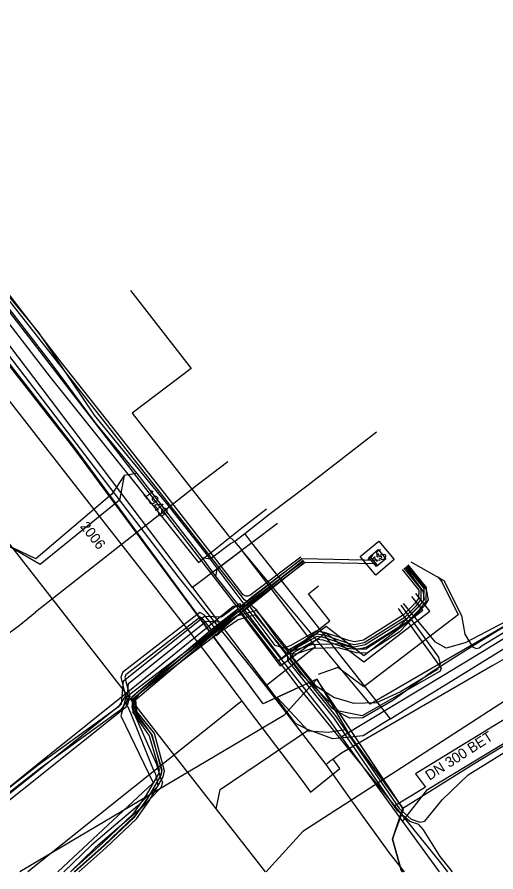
# Model space of a CAD drawing. Extents: x -600391 to -599491, y -1160176 to -1159402.
# Drawn here: x -600182.8 to -600145.4, y -1160176.1 to -1160109.3 of the extents above; entities that cross this region are included whole.
import ezdxf

# ---------------------------------------------------------------- set-up
doc = ezdxf.new("R2010")
doc.units = 0
for name, color, linetype in [('25', 7, 'Continuous'), ('CETIN_linie', 7, 'Continuous'), ('Vrstva 12', 7, 'Continuous'), ('Vrstva 13', 7, 'Continuous'), ('Vrstva 15', 7, 'Continuous'), ('Vrstva 16', 7, 'Continuous'), ('Vrstva 19', 7, 'Continuous'), ('Vrstva 42', 7, 'Continuous'), ('Vrstva 43', 7, 'Continuous'), ('Vrstva 44', 7, 'Continuous'), ('Vrstva 45', 7, 'Continuous'), ('Vrstva 55', 7, 'Continuous'), ('Vrstva 58', 7, 'Continuous'), ('Vrstva 9', 7, 'Continuous')]:
    doc.layers.add(name, color=color, linetype=linetype)

# ---------------------------------------------------------------- blocks, each defined once
blk = doc.blocks.new('NN640')
at = {"layer": '25'}
for points in [[(-1.89, 1.89), (1.89, 1.89)], [(-1.89, -1.89), (-1.89, 1.89)], [(1.89, 1.89), (1.89, -1.89)], [(-1.26, 0.79), (-0.22, 0.79)], [(-0.73, 0.79), (-0.73, -0.79)], [(1.2, 0.66), (0.94, 0.79), (0.66, 0.79), (0.41, 0.66), (0.28, 0.47), (0.28, 0.41), (0.41, 0.22), (1.13, -0.16), (1.26, -0.32), (1.26, -0.47), (1.13, -0.66), (0.91, -0.79), (0.63, -0.79), (0.5, -0.73), (0.28, -0.6)], [(1.89, -1.89), (-1.89, -1.89)]]:
    blk.add_lwpolyline(points, dxfattribs=at)
blk = doc.blocks.new('VN640')
at = {"layer": '25'}
for points in [[(-1.89, 1.89), (1.89, 1.89)], [(-1.89, -1.89), (-1.89, 1.89)], [(-1.26, 0.79), (-0.22, 0.79)], [(-0.73, 0.79), (-0.73, -0.79)], [(1.2, 0.66), (0.94, 0.79), (0.66, 0.79), (0.41, 0.66), (0.28, 0.47), (0.28, 0.41), (0.41, 0.22), (1.13, -0.16), (1.26, -0.32), (1.26, -0.47), (1.13, -0.66), (0.91, -0.79), (0.63, -0.79), (0.5, -0.73), (0.28, -0.6)], [(1.89, 1.89), (1.89, -1.89)], [(1.89, -1.89), (-1.89, -1.89)]]:
    blk.add_lwpolyline(points, dxfattribs=at)

msp = doc.modelspace()

# ---------------------------------------------------------------- linework, layer by layer
at = {"layer": 'CETIN_linie'}
for p, q in [((-600160.041, -1160145.829), (-600154.702, -1160141.703)), ((-600173.44, -1160144.95), (-600174.41, -1160145.12)), ((-600173.44, -1160144.95), (-600168.34, -1160151.51)), ((-600163.02, -1160148.09), (-600160.041, -1160145.829)), ((-600165, -1160149.65), (-600163.02, -1160148.09)), ((-600162.44, -1160148.85), (-600164.44, -1160150.36)), ((-600165.79, -1160150.27), (-600165, -1160149.65)), ((-600165.79, -1160150.27), (-600165.23, -1160150.94)), ((-600164.44, -1160150.36), (-600165, -1160149.65)), ((-600164.44, -1160150.36), (-600169.07, -1160153.86)), ((-600153.62, -1160164.12), (-600164.44, -1160150.36)), ((-600168.34, -1160151.51), (-600167.26, -1160153.04)), ((-600169.07, -1160153.86), (-600163.31, -1160161.48)), ((-600146.43, -1160159.67), (-600143.85, -1160158.08)), ((-600148.06, -1160160.68), (-600146.43, -1160159.67)), ((-600152.25, -1160163.27), (-600148.06, -1160160.68)), ((-600153.62, -1160164.12), (-600152.25, -1160163.27)), ((-600153.62, -1160164.12), (-600154.13, -1160164.44)), ((-600158.11, -1160165.69), (-600160.03, -1160164.97)), ((-600154.13, -1160164.44), (-600155.76, -1160165.44)), ((-600155.76, -1160165.44), (-600158.11, -1160165.69)), ((-600157.46, -1160165.52), (-600152.67, -1160172.13)), ((-600167.22, -1160171.18), (-600163.391, -1160176.079)), ((-600152.67, -1160172.13), (-600149.807, -1160176.079))]:
    msp.add_line(p, q, dxfattribs=at)
for points in [[(-600155.82, -1159824.25), (-600131.59, -1159876.14), (-600105.43, -1159931.66), (-600079.78, -1159985.02), (-600054.68, -1160038.07), (-600031.21, -1160088.32), (-600065.96, -1160109.81), (-600092.69, -1160126.24), (-600115.43, -1160139.89), (-600155.2, -1160162.97), (-600165.23, -1160150.94)], [(-600267.76, -1160025.17), (-600244.25, -1160055.86), (-600225.67, -1160079.89), (-600215.81, -1160092.29), (-600192.29, -1160121.78), (-600180.19, -1160137.43), (-600168.62, -1160151.9), (-600165.36, -1160149.31), (-600163.31, -1160147.71)], [(-600225.43, -1160097.28), (-600224.31, -1160097.79), (-600223.76, -1160098.18), (-600216.62, -1160107.61), (-600209.03, -1160117.53), (-600185.54, -1160147.75), (-600167.22, -1160171.18)], [(-600180.83, -1160138.31), (-600184.6, -1160133.37), (-600195.65, -1160118.9), (-600200.37, -1160112.86)], [(-600194.75, -1160117.41), (-600192.3, -1160120.58), (-600180.04, -1160136.48), (-600176.68, -1160141), (-600173.44, -1160144.95)], [(-600173.91, -1160130.65), (-600169.19, -1160136.75), (-600173.79, -1160140.24), (-600166.26, -1160149.83), (-600165.79, -1160150.27)], [(-600169.07, -1160153.86), (-600172.42, -1160149.43), (-600180.83, -1160138.31)], [(-600157.46, -1160165.52), (-600149.48, -1160160.71), (-600146.43, -1160158.86), (-600140.69, -1160155.35), (-600136.94, -1160153.08), (-600132.2, -1160150.2), (-600129.49, -1160148.59), (-600120.28, -1160143.04)], [(-600174.41, -1160145.12), (-600174.77, -1160147.05), (-600180.97, -1160152.06), (-600183.71, -1160150.47)], [(-600174.41, -1160145.12), (-600175.38, -1160146.58), (-600181.31, -1160151.62), (-600183.71, -1160150.47)], [(-600168.34, -1160151.51), (-600167.7, -1160151.63), (-600166.1, -1160150.43), (-600165.79, -1160150.27)], [(-600167.26, -1160153.04), (-600167.16, -1160152.4), (-600165.44, -1160151.1), (-600165.23, -1160150.94)], [(-600163.31, -1160161.48), (-600159.47, -1160158.46), (-600165.23, -1160150.94)], [(-600167.26, -1160153.04), (-600158.35, -1160164.29), (-600157.46, -1160165.52)], [(-600152.67, -1160172.13), (-600150.73, -1160169.64), (-600135.02, -1160160.13)], [(-600163.31, -1160161.48), (-600161.05, -1160164.47), (-600160.03, -1160164.97)], [(-600167.22, -1160171.18), (-600166.92, -1160169.63), (-600160.98, -1160165.62), (-600160.03, -1160164.97)]]:
    msp.add_lwpolyline(points, dxfattribs=at)
at = {"layer": 'Vrstva 13'}
for p, q in [((-600145.613, -1160159.966), (-600157.44, -1160166.8)), ((-600157.44, -1160166.8), (-600158.1, -1160167.28)), ((-600158.656, -1160167.697), (-600158.4, -1160167.489)), ((-600158.1, -1160167.28), (-600158.4, -1160167.489)), ((-600157.9, -1160167.54), (-600158.1, -1160167.28)), ((-600158.656, -1160167.697), (-600156.519, -1160170.698))]:
    msp.add_line(p, q, dxfattribs=at)
for points in [[(-600224.89, -1160086.22), (-600223.66, -1160087.79), (-600219.48, -1160093.03), (-600208.78, -1160106.62), (-600205.17, -1160111.23), (-600199.082, -1160119.045), (-600197.73, -1160120.78), (-600193.89, -1160125.68), (-600192.77, -1160127.135), (-600192.48, -1160127.51), (-600191.95, -1160128.2), (-600186.44, -1160135.41), (-600179, -1160144.94), (-600171.696, -1160154.271), (-600171.65, -1160154.33), (-600167.97, -1160159.08), (-600165.22, -1160162.741), (-600160.551, -1160168.918), (-600159.86, -1160169.84), (-600157.58, -1160168), (-600157.9, -1160167.54)], [(-600219.33, -1160089.71), (-600216.29, -1160093.64), (-600198.339, -1160116.482), (-600192.274, -1160124.216), (-600191.1, -1160125.733), (-600170.22, -1160153.004), (-600164.3, -1160160.4), (-600163.344, -1160161.593), (-600158.656, -1160167.697)], [(-600042.25, -1160097.39), (-600052.6, -1160103.47), (-600064.71, -1160110.88), (-600066.172, -1160111.772), (-600066.792, -1160112.144), (-600082.92, -1160121.92), (-600087, -1160124.324), (-600092.5, -1160127.56), (-600094.34, -1160128.629), (-600095.953, -1160129.604), (-600096.277, -1160129.802), (-600104.962, -1160135.247), (-600109.33, -1160137.828), (-600116.469, -1160142.124), (-600119.243, -1160143.708), (-600125.778, -1160147.731), (-600143.681, -1160158.835), (-600143.979, -1160159.03), (-600145.613, -1160159.966)], [(-600165.22, -1160162.741), (-600165.426, -1160162.904), (-600181.93, -1160176.079)], [(-600156.519, -1160170.698), (-600153.667, -1160174.672), (-600152.557, -1160176.079)]]:
    msp.add_lwpolyline(points, dxfattribs=at)
at = {"layer": 'Vrstva 16'}
for points in [[(-600149.134, -1160176.079), (-600149.77, -1160175.26), (-600153.28, -1160170.92), (-600160.82, -1160161.59), (-600162.37, -1160159.57), (-600191.81, -1160121.42), (-600215.03, -1160091.66), (-600218.37, -1160087.39), (-600241.27, -1160058.04), (-600268.45, -1160023.15), (-600268.66, -1160022.86), (-600279.96, -1160008.45), (-600285.15, -1160001.76), (-600292.76, -1159991.95), (-600306.26, -1159974.55), (-600310.89, -1159968.58), (-600323.17, -1159952.95), (-600331.19, -1159942.75), (-600331.3, -1159942.61), (-600336.91, -1159935.47), (-600352.95, -1159915.04), (-600356.32, -1159910.78), (-600372.09, -1159890.83), (-600376.451, -1159885.301)], [(-600038.85, -1160100.28), (-600041.83, -1160102.09), (-600051.25, -1160107.79), (-600062.14, -1160114.39), (-600066.71, -1160117.16), (-600067.2, -1160117.45), (-600074.9, -1160122.11), (-600082.66, -1160126.76), (-600085.11, -1160128.23), (-600087.28, -1160129.53), (-600093.47, -1160133.24), (-600094.95, -1160134.13), (-600101.02, -1160137.76), (-600106.62, -1160141.12), (-600113.2, -1160145.07), (-600115.54, -1160146.47), (-600124.72, -1160151.97), (-600127.78, -1160153.8), (-600151.67, -1160168.43), (-600150.87, -1160169.45), (-600151.29, -1160169.71)], [(-600162.37, -1160159.57), (-600158.36, -1160156.47), (-600160.03, -1160154.35), (-600159.24, -1160153.73)], [(-600151.29, -1160169.71), (-600153.28, -1160170.92)]]:
    msp.add_lwpolyline(points, dxfattribs=at)
at = {"layer": 'Vrstva 19'}
for points in [[(-600166.33, -1160144.05), (-600168.71, -1160145.88)], [(-600168.71, -1160145.88), (-600181.34, -1160155.787)], [(-600195.116, -1160165.979), (-600182.616, -1160156.82), (-600181.911, -1160156.255), (-600181.637, -1160156.017), (-600181.34, -1160155.787)]]:
    msp.add_lwpolyline(points, dxfattribs=at)
at = {"layer": 'Vrstva 42'}
for points in [[(-600246.552, -1160115.414), (-600239.241, -1160109.519), (-600237.541, -1160111.431), (-600223.338, -1160130.385), (-600221.756, -1160136.694), (-600216.842, -1160142.929), (-600214.427, -1160145.992), (-600205.901, -1160156.959), (-600210.402, -1160160.475), (-600210.279, -1160160.633), (-600210.156, -1160160.791), (-600205.655, -1160157.275), (-600192.327, -1160174.418), (-600191.04, -1160176.052), (-600174.619, -1160162.942), (-600174.457, -1160161.146), (-600168.134, -1160156.095), (-600166.808, -1160156.146), (-600165.41, -1160155.108), (-600162.138, -1160159.429), (-600158.651, -1160156.892), (-600155.694, -1160159.162), (-600151.097, -1160155.641), (-600151.957, -1160154.573)], [(-600152.701, -1160152.447), (-600151.412, -1160154.072), (-600151.428, -1160154.732), (-600151.745, -1160155.131), (-600152.589, -1160155.985), (-600155.732, -1160157.966), (-600156.437, -1160158.104), (-600156.87, -1160158.01), (-600158.76, -1160157.367), (-600159.45, -1160157.268), (-600161.39, -1160158.39), (-600161.94, -1160158.59), (-600162.61, -1160158.39), (-600167.94, -1160151.31), (-600170.99, -1160147.43), (-600176.74, -1160140.4), (-600181.09, -1160133.93), (-600186.24, -1160127.71)], [(-600152.035, -1160151.852), (-600149.443, -1160153.303), (-600148.072, -1160156.055), (-600147.8, -1160157.5), (-600147.214, -1160158.496), (-600146.914, -1160158.616), (-600146.684, -1160158.566), (-600146.466, -1160158.386), (-600129.424, -1160148.094)], [(-600152.458, -1160152.285), (-600151.099, -1160154.156), (-600150.995, -1160154.761), (-600151.21, -1160155.121), (-600153.122, -1160157.114), (-600155.547, -1160158.69), (-600156.232, -1160158.677), (-600157.649, -1160158.275), (-600159.778, -1160158.329), (-600161.076, -1160158.769), (-600161.55, -1160158.754), (-600163.52, -1160156.342), (-600164.07, -1160155.664), (-600165.641, -1160156.114), (-600166.954, -1160157.006), (-600167.171, -1160157.2), (-600168.167, -1160155.994), (-600168.509, -1160155.815), (-600174.542, -1160160.495), (-600174.685, -1160160.886), (-600174.305, -1160162.313), (-600174.893, -1160163.21), (-600181.04, -1160167.655), (-600189.363, -1160174.167)], [(-600152.313, -1160152.156), (-600150.819, -1160154.016), (-600150.681, -1160154.82), (-600150.97, -1160155.304), (-600152.929, -1160157.347), (-600155.461, -1160158.992), (-600156.277, -1160158.976), (-600157.687, -1160158.576), (-600159.725, -1160158.628), (-600161.031, -1160159.071), (-600161.696, -1160159.05), (-600163.753, -1160156.531), (-600164.178, -1160156.007), (-600165.512, -1160156.389), (-600166.769, -1160157.243), (-600167.204, -1160157.632), (-600168.36, -1160156.232), (-600168.477, -1160156.17), (-600174.29, -1160160.679), (-600174.371, -1160160.9), (-600173.981, -1160162.365), (-600174.672, -1160163.421), (-600180.86, -1160167.895), (-600189.172, -1160174.399)], [(-600152.38, -1160152.223), (-600151.009, -1160153.936), (-600151.031, -1160154.876), (-600151.445, -1160155.396), (-600152.337, -1160156.298), (-600155.583, -1160158.345), (-600156.441, -1160158.512), (-600156.977, -1160158.397), (-600158.853, -1160157.758), (-600159.37, -1160157.684), (-600160.975, -1160158.612), (-600161.341, -1160158.823), (-600161.45, -1160159.01), (-600161.43, -1160159.48), (-600157.864, -1160163.953), (-600152.904, -1160171.163), (-600152.009, -1160171.962), (-600151.332, -1160172.19), (-600150.94, -1160172.11), (-600149.59, -1160170.44), (-600147.54, -1160168.49), (-600141.72, -1160164.88)], [(-600144.595, -1160156.863), (-600146.94, -1160158.29), (-600150.4, -1160160.47), (-600153.44, -1160162.7), (-600155.78, -1160164.03), (-600156.8, -1160164.08), (-600157.8, -1160163.54), (-600158.132, -1160163.301), (-600161.233, -1160159.406), (-600161.248, -1160159.06), (-600161.127, -1160158.926), (-600159.33, -1160157.892), (-600158.9, -1160157.953), (-600157.03, -1160158.59), (-600156.232, -1160158.677), (-600155.507, -1160158.534), (-600152.211, -1160156.455), (-600151.295, -1160155.529), (-600150.832, -1160154.948), (-600150.808, -1160153.868), (-600152.224, -1160152.098)], [(-600148.782, -1160176.079), (-600149.74, -1160174.88), (-600151.04, -1160172.79), (-600151.397, -1160172.382), (-600152.111, -1160172.138), (-600153.056, -1160171.297), (-600158.047, -1160164.04), (-600161.627, -1160159.554), (-600161.652, -1160158.96), (-600161.489, -1160158.68), (-600161.081, -1160158.444), (-600159.41, -1160157.476), (-600158.807, -1160157.562), (-600156.923, -1160158.203), (-600156.439, -1160158.308), (-600155.658, -1160158.155), (-600152.463, -1160156.142), (-600151.595, -1160155.264), (-600151.229, -1160154.804), (-600151.211, -1160154.004), (-600152.536, -1160152.348)], [(-600149.91, -1160153.034), (-600149.613, -1160153.411), (-600148.325, -1160155.996), (-600155.707, -1160161.614), (-600157.716, -1160160.101), (-600159.265, -1160160.665)], [(-600190.433, -1160176.079), (-600174.235, -1160163.148), (-600174.073, -1160161.352), (-600168, -1160156.501), (-600166.682, -1160156.552), (-600165.49, -1160155.666), (-600162.22, -1160159.983), (-600158.658, -1160157.391), (-600155.694, -1160159.666), (-600150.529, -1160155.71), (-600151.639, -1160154.329)]]:
    msp.add_lwpolyline(points, dxfattribs=at)
at = {"layer": 'Vrstva 44'}
for points in [[(-600160.621, -1160151.483), (-600164.61, -1160154.49), (-600164.75, -1160154.55), (-600164.92, -1160154.53), (-600165.13, -1160154.43), (-600167.52, -1160151.31), (-600171.43, -1160146.29), (-600175.79, -1160140.75), (-600179.33, -1160136.25), (-600182.1, -1160132.67), (-600186.25, -1160127.32), (-600191.99, -1160119.95), (-600198.1, -1160112.38), (-600204.78, -1160103.69), (-600209.2, -1160098.08), (-600214.66, -1160091.39), (-600216.44, -1160089.98), (-600217.86, -1160088.43), (-600221.95, -1160082.93), (-600222.23, -1160082.56), (-600222.64, -1160080.93), (-600222.7, -1160080.75), (-600225.12, -1160077.51), (-600230.17, -1160070.83)], [(-600154.424, -1160151.765), (-600160.509, -1160151.629), (-600164.48, -1160154.64), (-600167.79, -1160157.48), (-600173.52, -1160161.89), (-600174.29, -1160162.46), (-600174.689, -1160163.876), (-600172.151, -1160169.125), (-600179.587, -1160176.079)], [(-600160.384, -1160151.792), (-600164.37, -1160154.77), (-600167.66, -1160157.61), (-600173.41, -1160162.06), (-600174.07, -1160162.71), (-600174.18, -1160163.07), (-600173.93, -1160163.64), (-600172.2, -1160167.94), (-600171.98, -1160168.45), (-600171.84, -1160169.05), (-600171.8, -1160169.37), (-600173.36, -1160170.92), (-600176.97, -1160174), (-600179.135, -1160176.079)], [(-600154.722, -1160152.014), (-600160.291, -1160151.913), (-600164.26, -1160154.92), (-600167.52, -1160157.79), (-600173.28, -1160162.19), (-600173.73, -1160162.79), (-600173.83, -1160163.18), (-600173.72, -1160163.55), (-600171.88, -1160167.65), (-600171.57, -1160168.72), (-600171.43, -1160169.1), (-600171.56, -1160169.5), (-600173.09, -1160171.1), (-600176.67, -1160174.21), (-600178.619, -1160176.079)], [(-600178.262, -1160176.079), (-600175.975, -1160174.045), (-600173.61, -1160171.8), (-600172.621, -1160170.425), (-600171.552, -1160168.584), (-600171.479, -1160168.183), (-600172.228, -1160165.365), (-600173.624, -1160163.628), (-600173.711, -1160162.526), (-600167.47, -1160157.251), (-600165.538, -1160155.78), (-600160.448, -1160151.73)], [(-600177.96, -1160176.079), (-600175.839, -1160174.193), (-600173.464, -1160171.938), (-600172.453, -1160170.533), (-600171.362, -1160168.654), (-600171.275, -1160168.175), (-600172.046, -1160165.273), (-600173.43, -1160163.55), (-600173.503, -1160162.612), (-600167.344, -1160157.407), (-600165.416, -1160155.938), (-600160.326, -1160151.888)]]:
    msp.add_lwpolyline(points, dxfattribs=at)
at = {"layer": 'Vrstva 55'}
for points in [[(-600159.37, -1160161.02), (-600163.57, -1160162.94), (-600178.28, -1160142.933), (-600197.299, -1160118.521), (-600212.697, -1160098.724), (-600214.119, -1160096.9), (-600217.08, -1160091.68), (-600222.93, -1160082.91), (-600226.85, -1160080.74), (-600230.45, -1160076.02), (-600247.641, -1160053.846), (-600267.85, -1160028.08), (-600281.812, -1160010.273), (-600299.508, -1159987.183)], [(-600159.37, -1160161.02), (-600162.95, -1160162.67), (-600163.57, -1160162.94), (-600178.36, -1160142.986), (-600192.39, -1160125.04), (-600203.84, -1160111.02), (-600214.66, -1160097.11), (-600217.08, -1160091.68), (-600222.93, -1160082.91), (-600226.85, -1160080.74), (-600230.45, -1160076.02), (-600230.45, -1160076.94), (-600237.55, -1160083.37), (-600235.29, -1160086.88), (-600234.96, -1160088.55), (-600235.88, -1160090.06), (-600243.77, -1160096.03)], [(-600159.37, -1160161.02), (-600156.75, -1160165.53), (-600152.66, -1160171.11), (-600147.15, -1160167.67), (-600130.6, -1160157.61), (-600123.522, -1160153.492), (-600116.45, -1160148.95), (-600098.338, -1160138.451), (-600087.7, -1160131.98), (-600078.75, -1160126.66), (-600071.881, -1160122.369), (-600055.58, -1160112.48), (-600048.047, -1160107.868), (-600038.81, -1160102.88), (-600036.34, -1160102.75), (-600034.65, -1160103.14), (-600032.77, -1160104.18), (-600030.5, -1160108.33), (-600020.96, -1160103.72), (-600020.19, -1160103.79)], [(-600159.37, -1160161.02), (-600161.937, -1160163.873), (-600182.575, -1160176.079)], [(-600159.37, -1160161.02), (-600162.47, -1160162.45), (-600160.05, -1160165.05), (-600158.45, -1160165.16), (-600157.13, -1160164.95), (-600152.66, -1160171.11), (-600153.45, -1160173.52), (-600152.77, -1160175.95), (-600152.666, -1160176.079)], [(-600152.66, -1160176.079), (-600152.77, -1160175.95), (-600153.45, -1160173.52), (-600152.66, -1160171.11), (-600159.37, -1160161.02)], [(-600152.669, -1160176.079), (-600152.77, -1160175.95), (-600153.45, -1160173.52), (-600152.61, -1160171.21), (-600159.37, -1160161.02)]]:
    msp.add_lwpolyline(points, dxfattribs=at)
at = {"layer": 'Vrstva 58'}
for points in [[(-600152.816, -1160155.247), (-600149.861, -1160159.292), (-600149.734, -1160159.861), (-600149.948, -1160160.271), (-600152.824, -1160162.001), (-600154.716, -1160162.875), (-600156.47, -1160162.913), (-600156.971, -1160162.768), (-600158.029, -1160162.46), (-600159.391, -1160161.608), (-600159.936, -1160160.912), (-600162.585, -1160157.659), (-600164.043, -1160155.634), (-600165.021, -1160154.824), (-600214.84, -1160091.439), (-600216.589, -1160090.02), (-600218.109, -1160088.272), (-600222.441, -1160082.519), (-600222.948, -1160080.77), (-600256.663, -1160038.315), (-600300.347, -1159981.753)], [(-600160.539, -1160151.611), (-600165.638, -1160155.64), (-600167.539, -1160157.121), (-600173.828, -1160162.423), (-600173.743, -1160163.615), (-600172.458, -1160165.453), (-600171.689, -1160168.116), (-600171.733, -1160168.416), (-600172.691, -1160170.095), (-600173.733, -1160171.563), (-600176.115, -1160173.836), (-600178.614, -1160176.079)], [(-600160.415, -1160151.767), (-600165.515, -1160155.798), (-600167.414, -1160157.277), (-600173.624, -1160162.513), (-600173.55, -1160163.542), (-600172.275, -1160165.365), (-600171.485, -1160168.102), (-600171.54, -1160168.482), (-600172.522, -1160170.203), (-600173.581, -1160171.695), (-600175.979, -1160173.982), (-600178.314, -1160176.079)], [(-600153.003, -1160155.509), (-600149.65, -1160160.166), (-600149.735, -1160160.405), (-600155.82, -1160163.89), (-600157.66, -1160163.53), (-600160.562, -1160160.656), (-600164.66, -1160155.26), (-600165.9, -1160155.35), (-600173.46, -1160161.49), (-600181.19, -1160167.69), (-600188.29, -1160173.44), (-600190.64, -1160175.07), (-600190.288, -1160176.079)], [(-600144.5, -1160156.47), (-600147.79, -1160158.18), (-600149.27, -1160158.61), (-600150.1, -1160158.14), (-600152.59, -1160155.1)]]:
    msp.add_lwpolyline(points, dxfattribs=at)
at = {"layer": 'Vrstva 9'}
for points in [[(-600131.98, -1160154.53), (-600133.544, -1160155.54), (-600134.211, -1160155.97), (-600142.417, -1160161.268), (-600151.339, -1160167.028), (-600151.874, -1160167.373), (-600157.026, -1160170.7), (-600157.973, -1160171.311), (-600160.45, -1160172.91)], [(-600160.45, -1160172.91), (-600162.566, -1160175.236), (-600162.61, -1160175.284), (-600163.333, -1160176.079)]]:
    msp.add_lwpolyline(points, dxfattribs=at)

# ---------------------------------------------------------------- block references
at = {"layer": 'Vrstva 43', "xscale": 0.49999999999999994, "yscale": 0.5, "rotation": 40}
msp.add_blockref('NN640', (-600154.647, -1160151.564), dxfattribs=at)
at = {"layer": 'Vrstva 45', "xscale": 0.24999999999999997, "yscale": 0.25, "rotation": 40}
msp.add_blockref('VN640', (-600154.647, -1160151.564), dxfattribs=at)

# ---------------------------------------------------------------- texts
at = {"layer": 'Vrstva 12'}
msp.add_text('DN 300 BET', height=0.8, rotation=32.83048, dxfattribs=at).set_placement((-600150.574, -1160168.966))
at = {"layer": 'Vrstva 15'}
for s, rotation, p in [('1949', 307.44915, (-600172.968, -1160146.572)), ('2006', 308.07941, (-600177.906, -1160149.095))]:
    msp.add_text(s, height=0.8, rotation=rotation, dxfattribs=at).set_placement(p)

doc.saveas('drawing.dxf')
